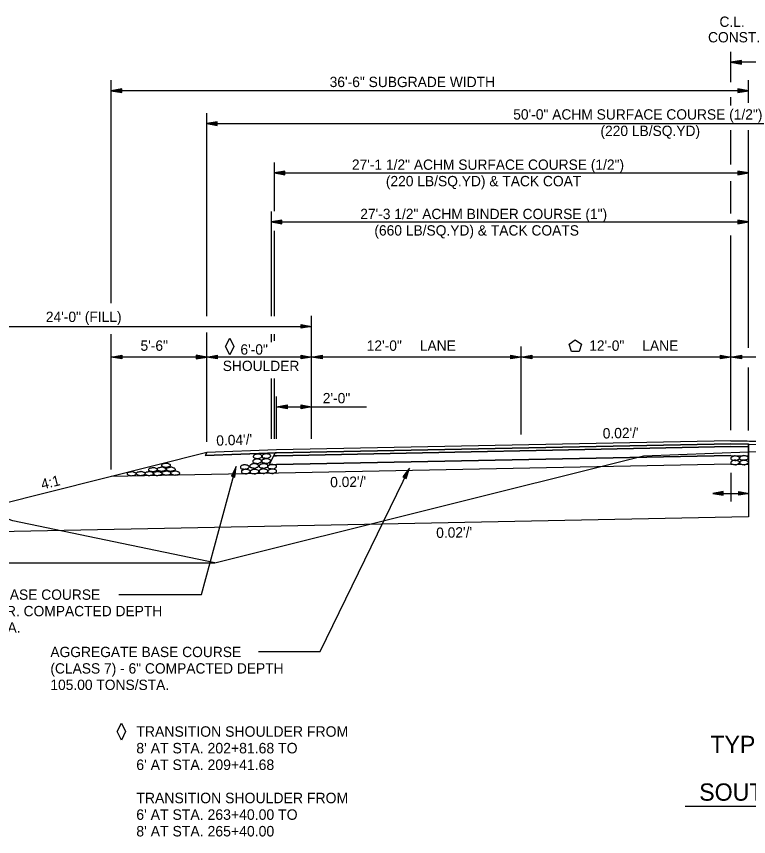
# Model space of a CAD drawing. Extents: x 1398565 to 1398920, y 1968324 to 1968581.
# Drawn here: x 1398600.91 to 1398642.8, y 1968324.5 to 1968371.41 of the extents above; entities that cross this region are included whole.
import ezdxf

# ---------------------------------------------------------------- set-up
doc = ezdxf.new("R2010")
doc.units = 0
for name, color, linetype in [('1', 7, 'Continuous'), ('10', 7, 'Continuous'), ('19', 7, 'Continuous'), ('42', 7, 'Continuous'), ('7', 7, 'Continuous'), ('Level 1', 7, 'Continuous')]:
    doc.layers.add(name, color=color, linetype=linetype)

# ---------------------------------------------------------------- blocks, each defined once
blk = doc.blocks.new('ROCKS')
at = {"layer": '1'}
blk.add_spline([(0.013, 0.06), (0.053, 0.053), (0.107, 0.033), (0.133, 0.013), (0.133, -0.007), (0.12, -0.033), (0.107, -0.04), (0.073, -0.053), (0.033, -0.067), (0.013, -0.067), (-0.02, -0.06), (-0.06, -0.053), (-0.087, -0.047), (-0.113, -0.02), (-0.113, -0.007), (-0.107, 0.02), (-0.087, 0.033), (-0.067, 0.047), (-0.033, 0.053), (-0.02, 0.06), (0.013, 0.06)], degree=3, dxfattribs=at)
blk = doc.blocks.new('4TO1 ABC')
at = {"layer": '1', "xscale": 0.1312491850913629, "yscale": 0.1312491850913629, "rotation": 180}
for p in [(0.00175, -0.00875), (-0.03325, -0.0385), (-0.016625, -0.023625), (0, -0.0385), (0.018375, -0.023625), (0.051625, -0.025375), (0.034125, -0.04025), (0.06475, -0.04025), (0.098, -0.04025), (0.133, -0.041125)]:
    blk.add_blockref('ROCKS', p, dxfattribs=at)

msp = doc.modelspace()

# ---------------------------------------------------------------- linework, layer by layer
at = {"layer": '10'}
for points in [[(1398613.112, 1968353.009), (1398613.353, 1968352.527), (1398613.112, 1968352.045), (1398612.871, 1968352.527)], [(1398632.534, 1968352.658), (1398632.883, 1968352.912), (1398633.233, 1968352.658), (1398633.099, 1968352.247), (1398632.668, 1968352.247)], [(1398606.913, 1968330.986), (1398607.154, 1968330.504), (1398606.913, 1968330.022), (1398606.672, 1968330.504)]]:
    msp.add_lwpolyline(points, close=True, dxfattribs=at)
at = {"layer": '19'}
for p, q in [((1398642.395, 1968368.891), (1398641.795, 1968368.786)), ((1398653.795, 1968368.786), (1398641.795, 1968368.786)), ((1398641.795, 1968368.786), (1398642.395, 1968368.681)), ((1398642.395, 1968368.836), (1398641.955, 1968368.801)), ((1398641.955, 1968368.771), (1398642.395, 1968368.731)), ((1398642.395, 1968368.681), (1398642.395, 1968368.891)), ((1398606.335, 1968355.014), (1398606.335, 1968367.751)), ((1398642.795, 1968366.467), (1398642.795, 1968367.751)), ((1398606.935, 1968367.256), (1398606.335, 1968367.151)), ((1398642.795, 1968367.151), (1398606.335, 1968367.151)), ((1398606.335, 1968367.151), (1398606.935, 1968367.046)), ((1398606.935, 1968367.201), (1398606.495, 1968367.166)), ((1398606.495, 1968367.136), (1398606.935, 1968367.096)), ((1398606.935, 1968367.046), (1398606.935, 1968367.256)), ((1398642.195, 1968367.256), (1398642.195, 1968367.046)), ((1398642.795, 1968367.151), (1398642.195, 1968367.256)), ((1398642.635, 1968367.166), (1398642.195, 1968367.201)), ((1398642.195, 1968367.046), (1398642.795, 1968367.151)), ((1398642.195, 1968367.096), (1398642.635, 1968367.136)), ((1398611.795, 1968354.262), (1398611.795, 1968365.876)), ((1398612.395, 1968365.381), (1398611.795, 1968365.276)), ((1398611.795, 1968365.276), (1398661.795, 1968365.276)), ((1398611.795, 1968365.276), (1398612.395, 1968365.171)), ((1398612.395, 1968365.326), (1398611.955, 1968365.291)), ((1398611.955, 1968365.261), (1398612.395, 1968365.221)), ((1398612.395, 1968365.171), (1398612.395, 1968365.381)), ((1398642.795, 1968352.446), (1398642.795, 1968364.909)), ((1398615.667, 1968360.263), (1398615.667, 1968363.054)), ((1398616.267, 1968362.559), (1398615.667, 1968362.454)), ((1398615.667, 1968362.454), (1398616.267, 1968362.349)), ((1398615.667, 1968362.454), (1398642.795, 1968362.454)), ((1398616.267, 1968362.504), (1398615.827, 1968362.469)), ((1398615.827, 1968362.439), (1398616.267, 1968362.399)), ((1398616.267, 1968362.349), (1398616.267, 1968362.559)), ((1398642.195, 1968362.559), (1398642.195, 1968362.349)), ((1398642.795, 1968362.454), (1398642.195, 1968362.559)), ((1398642.635, 1968362.469), (1398642.195, 1968362.504)), ((1398642.195, 1968362.349), (1398642.795, 1968362.454)), ((1398642.195, 1968362.399), (1398642.635, 1968362.439)), ((1398615.497, 1968354.262), (1398615.497, 1968360.256)), ((1398616.097, 1968359.761), (1398615.497, 1968359.656)), ((1398615.497, 1968359.656), (1398642.795, 1968359.656)), ((1398615.497, 1968359.656), (1398616.097, 1968359.551)), ((1398616.097, 1968359.706), (1398615.657, 1968359.671)), ((1398615.657, 1968359.641), (1398616.097, 1968359.601)), ((1398616.097, 1968359.551), (1398616.097, 1968359.761)), ((1398642.195, 1968359.761), (1398642.195, 1968359.551)), ((1398642.795, 1968359.656), (1398642.195, 1968359.761)), ((1398642.635, 1968359.671), (1398642.195, 1968359.706)), ((1398642.195, 1968359.551), (1398642.795, 1968359.656)), ((1398642.195, 1968359.601), (1398642.635, 1968359.641)), ((1398615.667, 1968354.262), (1398615.667, 1968359.142)), ((1398617.795, 1968347.258), (1398617.795, 1968354.28)), ((1398617.195, 1968353.575), (1398617.195, 1968353.785)), ((1398617.195, 1968353.785), (1398617.795, 1968353.68)), ((1398617.195, 1968353.73), (1398617.635, 1968353.695)), ((1398593.795, 1968353.68), (1398617.795, 1968353.68)), ((1398606.335, 1968345.501), (1398606.335, 1968353.239)), ((1398611.795, 1968347.076), (1398611.795, 1968353.321)), ((1398615.497, 1968352.774), (1398615.497, 1968353.239)), ((1398615.667, 1968352.856), (1398615.667, 1968353.239)), ((1398617.795, 1968353.68), (1398617.195, 1968353.575)), ((1398617.635, 1968353.665), (1398617.195, 1968353.625)), ((1398629.795, 1968347.498), (1398629.795, 1968352.521)), ((1398606.335, 1968351.921), (1398606.935, 1968352.026)), ((1398631.795, 1968351.921), (1398606.335, 1968351.921)), ((1398606.935, 1968351.816), (1398606.335, 1968351.921)), ((1398606.495, 1968351.936), (1398606.935, 1968351.971)), ((1398606.935, 1968351.866), (1398606.495, 1968351.906)), ((1398606.935, 1968352.026), (1398606.935, 1968351.816)), ((1398611.195, 1968352.026), (1398611.195, 1968351.816)), ((1398611.795, 1968351.921), (1398611.195, 1968352.026)), ((1398611.635, 1968351.936), (1398611.195, 1968351.971)), ((1398611.195, 1968351.816), (1398611.795, 1968351.921)), ((1398611.195, 1968351.866), (1398611.635, 1968351.906)), ((1398611.795, 1968351.921), (1398612.395, 1968352.026)), ((1398612.395, 1968351.816), (1398611.795, 1968351.921)), ((1398611.955, 1968351.936), (1398612.395, 1968351.971)), ((1398612.395, 1968351.866), (1398611.955, 1968351.906)), ((1398612.395, 1968352.026), (1398612.395, 1968351.816)), ((1398617.195, 1968351.816), (1398617.195, 1968352.026)), ((1398617.195, 1968352.026), (1398617.795, 1968351.921)), ((1398617.195, 1968351.971), (1398617.635, 1968351.936)), ((1398617.795, 1968351.921), (1398617.195, 1968351.816)), ((1398617.635, 1968351.906), (1398617.195, 1968351.866)), ((1398617.795, 1968351.921), (1398618.395, 1968352.026)), ((1398618.395, 1968351.816), (1398617.795, 1968351.921)), ((1398617.955, 1968351.936), (1398618.395, 1968351.971)), ((1398618.395, 1968351.866), (1398617.955, 1968351.906)), ((1398618.395, 1968352.026), (1398618.395, 1968351.816)), ((1398629.195, 1968351.816), (1398629.195, 1968352.026)), ((1398629.195, 1968352.026), (1398629.795, 1968351.921)), ((1398629.195, 1968351.971), (1398629.635, 1968351.936)), ((1398629.795, 1968351.921), (1398629.195, 1968351.816)), ((1398629.635, 1968351.906), (1398629.195, 1968351.866)), ((1398629.795, 1968351.921), (1398630.395, 1968352.026)), ((1398630.395, 1968351.816), (1398629.795, 1968351.921)), ((1398629.955, 1968351.936), (1398630.395, 1968351.971)), ((1398630.395, 1968351.866), (1398629.955, 1968351.906)), ((1398630.395, 1968352.026), (1398630.395, 1968351.816)), ((1398643.795, 1968351.921), (1398631.795, 1968351.921)), ((1398641.195, 1968351.816), (1398641.195, 1968352.026)), ((1398641.195, 1968352.026), (1398641.795, 1968351.921)), ((1398641.195, 1968351.971), (1398641.635, 1968351.936)), ((1398641.795, 1968351.921), (1398641.195, 1968351.816)), ((1398641.635, 1968351.906), (1398641.195, 1968351.866)), ((1398641.795, 1968351.921), (1398642.395, 1968352.026)), ((1398642.395, 1968351.816), (1398641.795, 1968351.921)), ((1398641.955, 1968351.936), (1398642.395, 1968351.971)), ((1398642.395, 1968351.866), (1398641.955, 1968351.906)), ((1398642.395, 1968352.026), (1398642.395, 1968351.816)), ((1398642.795, 1968347.718), (1398642.795, 1968351.326)), ((1398615.497, 1968347.258), (1398615.497, 1968350.697)), ((1398615.667, 1968347.258), (1398615.667, 1968350.697)), ((1398615.795, 1968347.258), (1398615.795, 1968349.679)), ((1398615.795, 1968349.079), (1398616.395, 1968349.184)), ((1398615.795, 1968349.079), (1398620.942, 1968349.079)), ((1398616.395, 1968348.974), (1398615.795, 1968349.079)), ((1398615.955, 1968349.094), (1398616.395, 1968349.129)), ((1398616.395, 1968349.024), (1398615.955, 1968349.064)), ((1398616.395, 1968349.184), (1398616.395, 1968348.974)), ((1398617.195, 1968348.974), (1398617.195, 1968349.184)), ((1398617.195, 1968349.184), (1398617.795, 1968349.079)), ((1398617.195, 1968349.129), (1398617.635, 1968349.094)), ((1398617.795, 1968349.079), (1398617.195, 1968348.974)), ((1398617.635, 1968349.064), (1398617.195, 1968349.024)), ((1398641.795, 1968347.138), (1398615.795, 1968346.618)), ((1398641.795, 1968347.138), (1398655.795, 1968346.858)), ((1398641.795, 1968346.971), (1398615.795, 1968346.451)), ((1398641.795, 1968346.804), (1398615.795, 1968346.284)), ((1398641.795, 1968346.971), (1398655.795, 1968346.691)), ((1398641.795, 1968346.804), (1398642.795, 1968346.784)), ((1398642.795, 1968346.784), (1398641.795, 1968346.804)), ((1398642.795, 1968346.951), (1398642.795, 1968345.492)), ((1398642.795, 1968346.284), (1398642.795, 1968346.784)), ((1398611.795, 1968346.458), (1398593.795, 1968341.958)), ((1398611.795, 1968346.458), (1398611.71, 1968346.287)), ((1398615.795, 1968346.451), (1398611.71, 1968346.287)), ((1398615.795, 1968346.618), (1398611.795, 1968346.458)), ((1398615.625, 1968346.277), (1398615.37, 1968345.767)), ((1398615.625, 1968346.277), (1398615.37, 1968345.767)), ((1398615.71, 1968346.447), (1398615.625, 1968346.277)), ((1398615.795, 1968346.284), (1398615.625, 1968346.277)), ((1398641.795, 1968346.304), (1398615.795, 1968345.784)), ((1398641.795, 1968346.304), (1398642.795, 1968346.284)), ((1398641.795, 1968346.304), (1398642.795, 1968346.284)), ((1398641.795, 1968345.802), (1398606.335, 1968345.093)), ((1398615.795, 1968345.784), (1398615.37, 1968345.767)), ((1398641.795, 1968345.802), (1398642.795, 1968345.782)), ((1398611.491, 1968338.346), (1398613.479, 1968345.669)), ((1398613.479, 1968345.669), (1398613.213, 1968345.121)), ((1398613.424, 1968345.519), (1398613.265, 1968345.109)), ((1398613.367, 1968345.079), (1398613.451, 1968345.511)), ((1398613.414, 1968345.065), (1398613.479, 1968345.669)), ((1398618.29, 1968335.086), (1398623.391, 1968345.566)), ((1398623.391, 1968345.566), (1398623.027, 1968345.077)), ((1398623.309, 1968345.429), (1398623.076, 1968345.056)), ((1398623.17, 1968345.007), (1398623.334, 1968345.416)), ((1398623.214, 1968344.984), (1398623.391, 1968345.566)), ((1398642.795, 1968345.492), (1398642.795, 1968342.782)), ((1398613.213, 1968345.121), (1398613.414, 1968345.065)), ((1398623.027, 1968345.077), (1398623.214, 1968344.984)), ((1398642.795, 1968342.782), (1398593.298, 1968341.792)), ((1398606.762, 1968338.346), (1398611.491, 1968338.346)), ((1398614.762, 1968335.086), (1398618.29, 1968335.086)), ((1398639.176, 1968326.249), (1398668.156, 1968326.249))]:
    msp.add_line(p, q, dxfattribs=at)
for points in [[(1398611.71, 1968346.287), (1398615.795, 1968346.451), (1398641.795, 1968346.971), (1398655.795, 1968346.691), (1398661.88, 1968346.447), (1398661.795, 1968346.618), (1398655.795, 1968346.858), (1398641.795, 1968347.138), (1398615.795, 1968346.618), (1398611.795, 1968346.458)], [(1398615.71, 1968346.447), (1398615.625, 1968346.277), (1398615.795, 1968346.284), (1398641.795, 1968346.804), (1398642.795, 1968346.784), (1398642.795, 1968346.951), (1398641.795, 1968346.971), (1398615.795, 1968346.451)]]:
    msp.add_lwpolyline(points, close=True, dxfattribs=at)
for points in [[(1398641.795, 1968346.804), (1398615.795, 1968346.284), (1398615.625, 1968346.277)], [(1398615.37, 1968345.767), (1398615.795, 1968345.784), (1398641.795, 1968346.304)]]:
    msp.add_lwpolyline(points, dxfattribs=at)
at = {"layer": '42'}
for p, q in [((1398641.795, 1968345.304), (1398641.795, 1968343.672)), ((1398641.347, 1968344.229), (1398640.747, 1968344.124)), ((1398640.747, 1968344.124), (1398641.347, 1968344.019)), ((1398640.747, 1968344.124), (1398642.842, 1968344.124)), ((1398641.347, 1968344.174), (1398640.907, 1968344.139)), ((1398640.907, 1968344.109), (1398641.347, 1968344.069)), ((1398641.347, 1968344.019), (1398641.347, 1968344.229)), ((1398642.242, 1968344.019), (1398642.242, 1968344.229)), ((1398642.242, 1968344.229), (1398642.842, 1968344.124)), ((1398642.242, 1968344.174), (1398642.682, 1968344.139)), ((1398642.842, 1968344.124), (1398642.242, 1968344.019)), ((1398642.682, 1968344.109), (1398642.242, 1968344.069))]:
    msp.add_line(p, q, dxfattribs=at)
for points in [[(1398642.795, 1968346.511), (1398653.795, 1968346.731)], [(1398565.772, 1968340.162), (1398612.268, 1968340.162), (1398636.795, 1968346.271), (1398642.795, 1968346.511)], [(1398612.268, 1968340.162), (1398600.713, 1968342.553), (1398598.177, 1968343.459), (1398594.756, 1968344.524), (1398582.596, 1968346.375), (1398577.897, 1968346.568), (1398565.981, 1968346.523)]]:
    msp.add_lwpolyline(points, dxfattribs=at)
at = {"layer": '7'}
for p, q in [((1398641.795, 1968367.643), (1398641.795, 1968369.386)), ((1398641.795, 1968366.303), (1398641.795, 1968366.795)), ((1398641.795, 1968362.942), (1398641.795, 1968364.909)), ((1398641.795, 1968360.126), (1398641.795, 1968361.985)), ((1398641.795, 1968347.738), (1398641.795, 1968358.869))]:
    msp.add_line(p, q, dxfattribs=at)

# ---------------------------------------------------------------- block references
at = {"layer": '19', "xscale": 14.999970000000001, "yscale": -14.999970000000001, "rotation": 180}
msp.add_blockref('4TO1 ABC', (1398609.475, 1968345.861), dxfattribs=at)
at = {"layer": 'Level 1', "xscale": 2.011654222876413, "yscale": 2.011654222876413, "rotation": 1.8263814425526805}
for p in [(1398614.69, 1968346.254), (1398615.189, 1968346.269), (1398642.015, 1968346.146), (1398642.514, 1968346.161), (1398613.952, 1968345.639), (1398614.496, 1968345.709), (1398614.663, 1968345.975), (1398615.029, 1968345.705), (1398615.175, 1968345.986), (1398615.52, 1968345.661), (1398642.015, 1968345.904), (1398642.52, 1968345.903), (1398614.012, 1968345.384), (1398614.516, 1968345.383), (1398615.021, 1968345.404), (1398615.526, 1968345.404)]:
    msp.add_blockref('ROCKS', p, dxfattribs=at)

# ---------------------------------------------------------------- texts
at = {"layer": '10'}
for s, height, rotation, p in [('24\'-0" (FILL)', 0.59001, 360, (1398602.593, 1968353.932)), ('5\'-6"', 0.59, 360, (1398608.009, 1968352.284)), ('12\'-0" ', 0.59, 360, (1398620.952, 1968352.284)), ('LANE', 0.59, 360, (1398623.991, 1968352.284)), ('12\'-0" ', 0.59, 360, (1398633.681, 1968352.284)), ('LANE', 0.59, 360, (1398636.72, 1968352.284)), ('6\'-0" ', 0.59, 360, (1398613.726, 1968352.066)), ('SHOULDER', 0.59, 360, (1398612.714, 1968351.126)), ('2\'-0"', 0.59, 360, (1398618.437, 1968349.282)), ('4:1', 0.59, 13.7364, (1398602.393, 1968344.348))]:
    msp.add_text(s, height=height, rotation=rotation, dxfattribs=at).set_placement(p)
at = {"layer": '19'}
msp.add_text('C.L.', height=0.59, dxfattribs=at).set_placement((1398641.135, 1968370.808))
for s, height, rotation, p in [('CONST.', 0.59, 360, (1398640.481, 1968369.92)), ("0.02'/'", 0.59, 1.1458, (1398634.462, 1968347.265)), ("0.04'/'", 0.59, 2.2906, (1398612.356, 1968346.849)), ("0.02'/'", 0.59, 1.1458, (1398618.868, 1968344.475)), ("0.02'/'", 0.59, 1.1458, (1398624.934, 1968341.579)), ('AGGREGATE BASE COURSE', 0.59001, 360, (1398594.788, 1968338.043)), ('(CLASS 7) - VAR. COMPACTED DEPTH', 0.59001, 360, (1398594.788, 1968337.103)), ('61.75 TONS/STA.', 0.59001, 360, (1398594.788, 1968336.163)), ('AGGREGATE BASE COURSE', 0.59001, 360, (1398602.852, 1968334.766)), ('(CLASS 7) - 6" COMPACTED DEPTH', 0.59001, 360, (1398602.852, 1968333.826)), ('105.00 TONS/STA.', 0.59001, 360, (1398602.852, 1968332.886)), ('TYPICAL SECTION OF IMPROVEMENT', 0.98999, 360, (1398640.613, 1968329.275)), ('SOUTHBOUND PASSING LANE (SITE 2)', 0.98999, 360, (1398639.977, 1968326.553))]:
    msp.add_text(s, height=height, rotation=rotation, dxfattribs=at).set_placement(p)
at = {"layer": '42'}
for s, p in [('36\'-6" SUBGRADE WIDTH', (1398618.832, 1968367.364)), ('50\'-0" ACHM SURFACE COURSE (1/2")', (1398629.336, 1968365.507)), ('(220 LB/SQ.YD)', (1398634.326, 1968364.567)), ('27\'-1 1/2" ACHM SURFACE COURSE (1/2")', (1398620.104, 1968362.633)), ('(220 LB/SQ.YD) & TACK COAT', (1398622.048, 1968361.693)), ('27\'-3 1/2" ACHM BINDER COURSE (1")', (1398620.582, 1968359.814)), ('(660 LB/SQ.YD) & TACK COATS', (1398621.39, 1968358.874))]:
    msp.add_text(s, height=0.59001, rotation=360, dxfattribs=at).set_placement(p)
for s, p in [('TRANSITION SHOULDER FROM', (1398607.768, 1968330.21)), ("8' AT STA. 202+81.68 TO", (1398607.768, 1968329.26)), ("6' AT STA. 209+41.68", (1398607.768, 1968328.31)), ('TRANSITION SHOULDER FROM', (1398607.768, 1968326.41)), ("6' AT STA. 263+40.00 TO", (1398607.768, 1968325.46)), ("8' AT STA. 265+40.00", (1398607.768, 1968324.51))]:
    msp.add_text(s, height=0.6, dxfattribs=at).set_placement(p)

doc.saveas('drawing.dxf')
